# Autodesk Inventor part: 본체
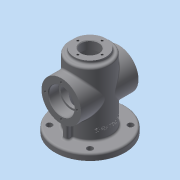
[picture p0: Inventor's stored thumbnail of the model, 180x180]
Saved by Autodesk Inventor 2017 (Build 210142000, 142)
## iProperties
Created: 2020-05
Part Number: 본체
Material: 알루미늄 6061
Document SubType Name: Modeling
Designer: mduedu
Density: 2.71 g/cm^3
Appearance: 기본값
Mass: 777.292 g
Surface Area: 687.933 cm^2
Volume: 286.824 cm^3
Author: mduedu
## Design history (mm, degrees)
sketch "스케치1"
  geometry: C1 r 32 at (0, 0); 1 further point
  constraints: 1 centre point, 1 coincident
  dimensions: "d0" = 64 diameter of C1
extrude "돌출1" new body sketch "스케치1" distance "d1" = 110; taper "d2" = 0 deg
feature "쉘1" dims "d3" = 8
fillet "모깎기1" dims "d4" = 3
fillet "모깎기2" dims "d5" = 3
sketch "스케치2"
  geometry: C1 r 25 at (0, 0); 1 further point
  constraints: 1 centre point, 1 coincident
  dimensions: "d6" = 50 diameter of C1
extrude "돌출2" join sketch "스케치2" distance "d7" = 5; taper "d8" = 0 deg
sketch "스케치3"
  geometry: C1 r 14 at (0, 0); 1 further point
  constraints: 1 centre point, 1 coincident
  dimensions: "d9" = 28 diameter of C1
extrude "돌출3" cut sketch "스케치3" stored distance "d10" = 5; taper "d11" = 0 deg
fillet "모깎기3" dims "d12" = 3
sketch "스케치4"
  geometry: C1 r 32 at (0, 0) reference; C2 r 55 at (0, 0); 1 further point
  constraints: 1 centre point, 1 coincident
  dimensions: "d13" = 110 diameter of C2
extrude "돌출4" join sketch "스케치4" distance "d14" = 10; taper "d15" = 0 deg
sketch "스케치5"
  geometry: L1 (0, 0)-(-31.82, 31.82); L2 (0, 0)-(-45, 0); A1 r 45 centre (0, 0) between (-31.82, 31.82) and (-45, 0); 1 further point
  constraints: 4 end point, 2 point on circle, 1 centre point, 1 coincident, 1 horizontal
  dimensions: "d16" = 90 diameter of A1; "d71" = 45 deg angle of L1 L2
hole "구멍1" sketch "스케치5" at (-31.82, 31.82) diameter "d17" = 9; stored, may be unused: countersink angle "d21" = 90 deg, drill point angle "d23" = 118 deg; dims "d18" = 6, "d19" = 4, "d20" = 2, "d22" = 8
fillet "모깎기4" dims "d27" = 3
node "작업 평면1"
sketch "스케치6"
  geometry: L1 (0, 55)-(0, -55) reference; C1 r 31 at (-65, 0); 2 further points
  constraints: 1 centre point, 1 horizontal alignment, 1 midpoint
  dimensions: "d31" = 62 diameter of C1; "d32" = 65 distance from line of C1.centre L1
extrude "돌출5" join sketch "스케치6" stored distance "d33" = 10; taper "d34" = 0 deg
fillet "모깎기5" dims "d35" = 3
sketch "스케치7"
  geometry: C1 r 31 at (0, 0) reference; C2 r 20 at (0, 0); 1 further point
  constraints: 1 centre point, 1 coincident
  dimensions: "d36" = 40 diameter of C2
extrude "돌출6" cut sketch "스케치7" distance "d37" = 16; taper "d38" = 0 deg
sketch "스케치8"
  geometry: C1 r 20 at (0, 0) reference; C2 r 17 at (0, 0); 1 further point
  constraints: 1 centre point, 1 coincident
  dimensions: "d39" = 34 diameter of C2
extrude "돌출7" cut sketch "스케치8" stored distance "d40" = 15; taper "d41" = 0 deg
fillet "모깎기6" dims "d42" = 0.3
chamfer "모따기1" distance "d43" = 1; stored, may be unused: second distance "d44" = 2, angle "d45" = 45 deg
chamfer "모따기2" distance "d46" = 1; stored, may be unused: second distance "d47" = 2, angle "d48" = 45 deg
sketch "스케치9" dims "d49" = 50
  geometry: C1 r 31 at (0, 0) reference; 3 further points
  constraints: 2 vertical alignment, 1 coincident, 2 other
hole "구멍2" sketch "스케치9" at (0, 25) diameter "d50" = 3.242; stored, may be unused: countersink angle "d54" = 90 deg, drill point angle "d56" = 118 deg; dims "d51" = 7, "d52" = 4, "d53" = 2, "d55" = 9
sketch "스케치10" dims "d60" = 38
  geometry: 3 further points
  constraints: 2 vertical alignment, 1 coincident, 2 other
hole "구멍3" sketch "스케치10" at (0, 19) diameter "d61" = 3.242; stored, may be unused: countersink angle "d65" = 90 deg, drill point angle "d67" = 118 deg; dims "d62" = 8, "d63" = 4, "d64" = 2, "d66" = 10
sketch "스케치11"
  geometry: L1 (32, 31)-(32, 13) reference; L2 (35, 10)-(52, 10) reference; L3 (55, 7)-(55, 0) reference; L4 (55, 0)-(24, 0) reference; L5 (24, 0)-(24, 48) reference; L6 (24, 48)-(29, 48) reference; L7 (29, 48)-(29, 45.3) reference; L8 (29.3, 45)-(44, 45) reference; L9 (44, 45)-(45, 44) reference; L10 (45, 44)-(45, 41.621) reference; L11 (45, 41.621)-(36, 41.621) reference; L12 (36, 41.621)-(35.026, 40) reference; L13 (35.026, 40)-(36, 38.379) reference; L14 (36, 38.379)-(45, 38.379) reference; L15 (45, 38.379)-(45, 34) reference; L16 (45, 34)-(35, 34) reference; L17 (-32, 13)-(-32, 31) reference; L18 (-35, 34)-(-45, 34) reference; L19 (-45, 34)-(-45, 38.379) reference; L20 (-45, 38.379)-(-36, 38.379) reference; L21 (-36, 38.379)-(-35.026, 40) reference; L22 (-35.026, 40)-(-36, 41.621) reference; L23 (-36, 41.621)-(-45, 41.621) reference; L24 (-45, 41.621)-(-45, 44) reference; L25 (-45, 44)-(-44, 45) reference; L26 (-44, 45)-(-29.3, 45) reference; L27 (-29, 45.3)-(-29, 48) reference; L28 (-29, 48)-(-24, 48) reference; L29 (-24, 48)-(-24, 0) reference; L30 (-24, 0)-(-55, 0) reference; L31 (-55, 0)-(-55, 7) reference; L32 (-52, 10)-(-35, 10) reference; L33 (-25, 113)-(-25, 115) reference; L34 (-25, 115)-(-20.621, 115) reference; L35 (-20.621, 115)-(-20.621, 105) reference; L36 (-20.621, 105)-(-19, 104.026) reference; L37 (-19, 104.026)-(-17.379, 105) reference; L38 (-17.379, 105)-(-17.379, 115) reference; L39 (-17.379, 115)-(-15, 115) reference; L40 (-15, 115)-(-14, 114) reference; L41 (-14, 114)-(-14, 102) reference; L42 (-14, 102)-(-21, 102) reference; L43 (-24, 99)-(-24, 82) reference; L44 (-24, 82)-(-29, 82) reference; L45 (-29, 82)-(-29, 84.7) reference; L46 (-29.3, 85)-(-44, 85) reference; L47 (-44, 85)-(-45, 86) reference; L48 (-45, 86)-(-45, 88.379) reference; L49 (-45, 88.379)-(-36, 88.379) reference; L50 (-36, 88.379)-(-35.026, 90) reference; L51 (-35.026, 90)-(-36, 91.621) reference; L52 (-36, 91.621)-(-45, 91.621) reference; L53 (-45, 91.621)-(-45, 96) reference; L54 (-45, 96)-(-35, 96) reference; L55 (-32, 99)-(-32, 107) reference; L56 (-29, 110)-(-28, 110) reference; L57 (28, 110)-(29, 110) reference; L58 (32, 107)-(32, 99) reference; L59 (35, 96)-(45, 96) reference; L60 (45, 96)-(45, 91.621) reference; L61 (45, 91.621)-(36, 91.621) reference; L62 (36, 91.621)-(35.026, 90) reference; L63 (35.026, 90)-(36, 88.379) reference; L64 (36, 88.379)-(45, 88.379) reference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; A1 r 3 centre (35, 13) between (32, 13) and (35, 10) reference; A2 r 3 centre (52, 7) between (55, 7) and (52, 10) reference; A3 r 0.3 centre (29.3, 45.3) between (29, 45.3) and (29.3, 45) reference; A4 r 0.3 centre (-29.3, 45.3) between (-29.3, 45) and (-29, 45.3) reference; A5 r 3 centre (-52, 7) between (-52, 10) and (-55, 7) reference; A6 r 3 centre (-35, 13) between (-35, 10) and (-32, 13) reference; A7 r 3 centre (-28, 113) between (-28, 110) and (-25, 113) reference; A8 r 3 centre (-21, 99) between (-21, 102) and (-24, 99) reference; A9 r 0.3 centre (-29.3, 84.7) between (-29, 84.7) and (-29.3, 85) reference; A10 r 3 centre (-29, 107) between (-29, 110) and (-32, 107) reference; A11 r 3 centre (28, 113) between (25, 113) and (28, 110) reference; A12 r 3 centre (29, 107) between (32, 107) and (29, 110) reference; A13 r 0.3 centre (29.3, 84.7) between (29.3, 85) and (29, 84.7) reference; A14 r 3 centre (21, 99) between (24, 99) and (21, 102) reference; 1 further point
  constraints: 2 end point, 1 midpoint, 1 perpendicular, 1 point on line, 4 other
  dimensions: "d73" = 5 distance between parallel lines of L81 L19
feature "리브1" sketch "스케치11" dims "d74" = 1, "d75" = 8, "d76" = 0, "d77" = 0, "d78" = 1, "d79" = 1
fillet "모깎기7" dims "d80" = 3
fillet "모깎기8" dims "d81" = 3
node "작업 평면2"
sketch "스케치12"
  geometry: 2 further points
  constraints: 1 vertical alignment, 1 other
  dimensions: "d83" = 25 distance of point (0, 25) point (0, 0)
feature "엠보싱1" sketch "스케치12" dims "d0" = 64, "d84" = 0.5, "d85" = 0
node "솔리드1"
pattern_circular "원형 패턴1" dims angle "d25" = 360 deg
mirror "대칭1"
mirror "대칭2"
pattern_circular "원형 패턴2" dims angle "d58" = 360 deg
mirror "대칭3"
pattern_circular "원형 패턴3" dims angle "d69" = 360 deg
mirror "대칭4"
node "투영된 루프1"
node "투영된 루프2"
node "절단 모서리 투영1"
other parameters: "d30" = -45
